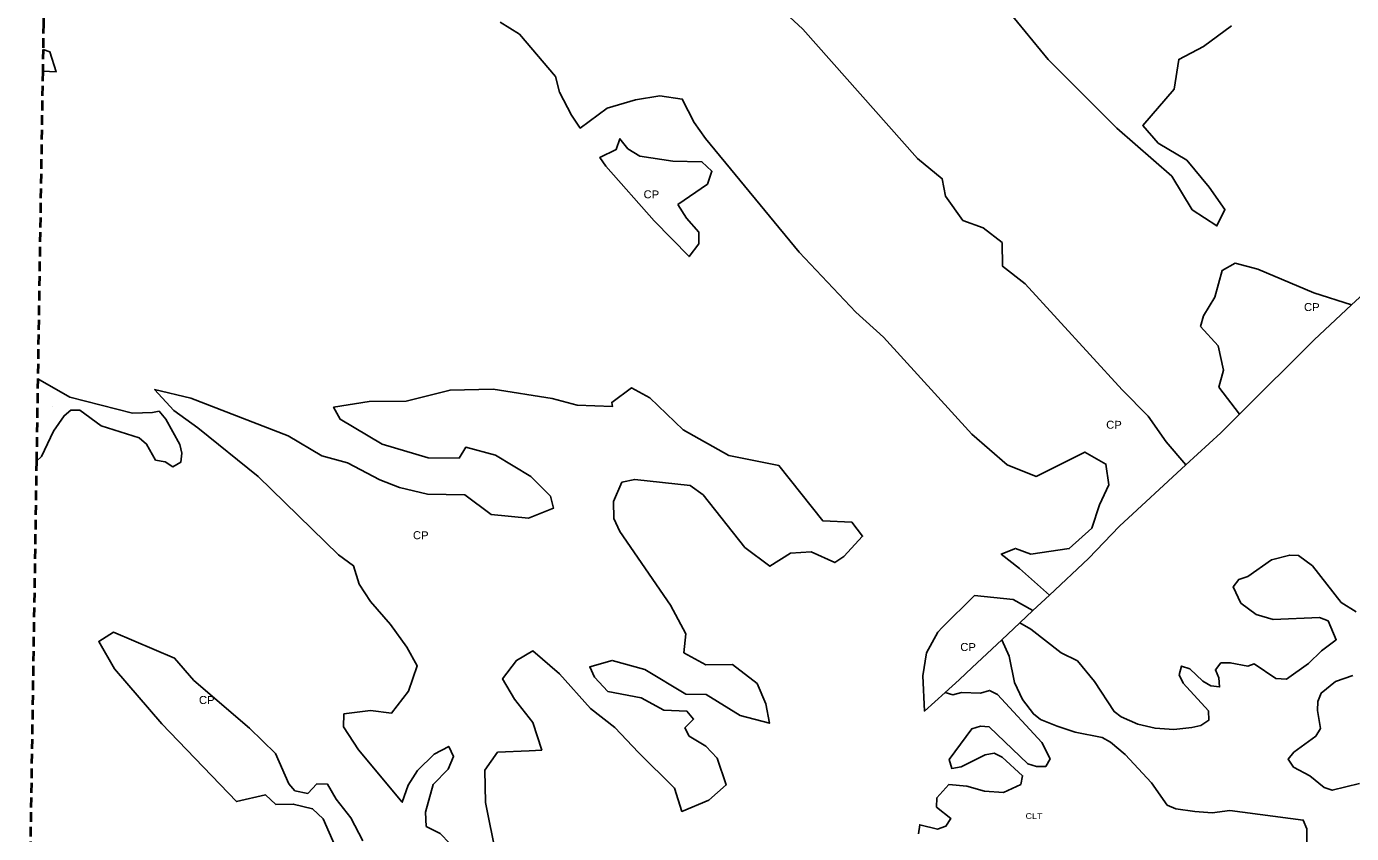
# Model space of a CAD drawing. Extents: x 713589 to 726391, y 7177764 to 7191819.
# Drawn here: x 713612 to 714671, y 7179591 to 7180236 of the extents above; entities that cross this region are included whole.
import ezdxf
from ezdxf.enums import TextEntityAlignment as Align

# ---------------------------------------------------------------- set-up
doc = ezdxf.new("R2010")
doc.units = 0
doc.header["$LTSCALE"] = 2.6
doc.linetypes.add('MEDIUM_DASHED', pattern=[4.5, 3, -1.5])
doc.layers.add('63', color=7, linetype='Continuous', lineweight=25)

msp = doc.modelspace()

# ---------------------------------------------------------------- linework, layer by layer
at = {"layer": '63'}
msp.add_line((714429.85, 7179781.5), (714416.59, 7179769.05), dxfattribs=at)
at = {"layer": '63', "linetype": 'MEDIUM_DASHED', "lineweight": 40}
for points in [[(713626.64, 7180327.97), (713625.21, 7180238.52), (713624.88, 7180217.79), (713624.6, 7180200.34)], [(713624.6, 7180200.34), (713620.67, 7179954.51), (713619.62, 7179888.54)], [(713619.62, 7179888.54), (713613.97, 7179534.19), (713611.65, 7179388.89)]]:
    msp.add_lwpolyline(points, dxfattribs=at)
at = {"layer": '63'}
for points in [[(714176.37, 7180286.4), (714232.62, 7180233.94), (714324.25, 7180130.72), (714344.11, 7180114.45), (714346.74, 7180100.53), (714360.62, 7180080.95), (714376.85, 7180075.29), (714392.08, 7180063.33), (714392.38, 7180044.44), (714410.25, 7180030.49), (714487.99, 7179945.52), (714508.84, 7179924.61), (714523.05, 7179904.04), (714538.93, 7179885.5)], [(714392.06, 7180254.56), (714428.78, 7180209.76), (714483.7, 7180154.98), (714527.71, 7180116.47), (714543.91, 7180089.6), (714563.77, 7180076.64), (714570.09, 7180089.88), (714557.53, 7180107.8), (714539.67, 7180129.37), (714516.82, 7180143), (714504.58, 7180156.94), (714529.49, 7180186.06), (714533.17, 7180209.92), (714553.07, 7180220.16), (714575.3, 7180236.69)], [(714429.85, 7179781.5), (714405.9, 7179802.82), (714391.28, 7179814.19), (714402.61, 7179818.74), (714414.86, 7179814.07), (714445.69, 7179818.66), (714463.62, 7179834.87), (714469.94, 7179853.75), (714477.26, 7179869.65), (714474.97, 7179886.22), (714458.08, 7179895.86), (714419.27, 7179876.37), (714396.09, 7179885.69), (714367.63, 7179910.26), (714297.17, 7179987.6), (714275, 7180007.85), (714229.67, 7180055.65), (714154.59, 7180146.58), (714145.67, 7180159.52), (714136.09, 7180178.1), (714118.19, 7180180.78), (714098.64, 7180177.5), (714076.09, 7180170.9), (714054.56, 7180154.94), (714047.58, 7180165.32), (714038, 7180183.56), (714034.7, 7180196.16), (714005.93, 7180230.01), (713990.37, 7180239.65)], [(713624.88, 7180217.79), (713630.41, 7180216.05), (713635.36, 7180199.81), (713624.6, 7180200.34)], [(714581.76, 7179926.16), (714565.21, 7179947.72), (714568.88, 7179961.3), (714564.61, 7179980.86), (714550.71, 7179996.13), (714553.05, 7180004.74), (714562.02, 7180019.64), (714568.02, 7180041.17), (714578.3, 7180046.79), (714596.52, 7180042.12), (714641.23, 7180023.15), (714671.36, 7180013.46)], [(714671.36, 7180013.46), (714681, 7180022.42)], [(714671.36, 7180013.46), (714641.5, 7179985.7), (714581.76, 7179926.16)], [(713619.62, 7179888.54), (713623.52, 7179892.19), (713633.12, 7179912.62), (713641.71, 7179924.81), (713647, 7179929.42), (713654.26, 7179929.41), (713671.39, 7179916.85), (713701.72, 7179907.23), (713707.65, 7179902.27), (713714.89, 7179889.4), (713722.47, 7179888.06), (713728.73, 7179884.09), (713735.01, 7179887.71), (713736.01, 7179894.97), (713734.37, 7179901.9), (713723.19, 7179922.04), (713717.68, 7179928.47), (713712.46, 7179927.59), (713696.55, 7179926.95), (713646.19, 7179939.63), (713620.67, 7179954.51)], [(714136.97, 7179913.63), (714110.17, 7179939.19), (714095.6, 7179947.17), (714079.68, 7179935.6), (714080.29, 7179932.27), (714052.16, 7179933.32), (714031.96, 7179938.66), (713984.91, 7179946.03), (713950.44, 7179945.42), (713915.3, 7179936.53), (713885.8, 7179936.25), (713857.29, 7179931.66), (713862.58, 7179922.04), (713896.02, 7179902.1), (713932.79, 7179891.1), (713957.64, 7179891.06), (713962.96, 7179899.67), (713986.81, 7179893.33), (714014.95, 7179876.38), (714030.83, 7179860.45), (714033.14, 7179850.83), (714013.24, 7179842.91), (713983.42, 7179845.94), (713962.23, 7179861.55), (713932.41, 7179862.27), (713909.88, 7179867.61), (713894.31, 7179873.6), (713868.49, 7179887.23), (713847.95, 7179892.9), (713820.8, 7179908.85), (713742.97, 7179938.81), (713714.14, 7179945.81), (713729.43, 7179929.2), (713748.56, 7179915.27), (713796.88, 7179876.41), (713861.07, 7179813.67), (713873.17, 7179804.88), (713877.6, 7179790.11), (713886.86, 7179776.18), (713902.74, 7179757.92)], [(714581.76, 7179926.16), (714566.81, 7179911.26), (714538.93, 7179885.5)], [(713987.27, 7179573.18), (713978.73, 7179615.62), (713978.11, 7179641.47), (713988.4, 7179655.7), (714013.73, 7179657), (714023.68, 7179657.51), (714016.61, 7179679.52), (714002.06, 7179698.1), (713992.48, 7179714.36), (714003.44, 7179729.25), (714016.71, 7179736.85), (714037.89, 7179718.59), (714062.7, 7179690.71), (714082.23, 7179675.43), (714101.09, 7179655.56), (714129.87, 7179626.97), (714135.8, 7179608.4), (714157.36, 7179617.31), (714171.3, 7179629.55), (714164.05, 7179651.1), (714155.11, 7179660.73), (714141.54, 7179668.71), (714138.24, 7179675.34), (714145.21, 7179682.29), (714139.91, 7179688.59), (714121.36, 7179689.29), (714103.15, 7179699.26), (714076.64, 7179704.28), (714066.05, 7179715.89), (714062.09, 7179724.18), (714080, 7179729.13), (714106.17, 7179721.79), (714138.95, 7179702.18), (714155.18, 7179701.83), (714182.33, 7179685.21), (714205.84, 7179678.93), (714202.89, 7179694.46), (714195.96, 7179710.71), (714176.43, 7179725.98), (714154.89, 7179725.69), (714137.34, 7179735.33), (714139.02, 7179750.57), (714126.8, 7179773.46), (714086.13, 7179832.18), (714081.51, 7179842.8), (714081.2, 7179856.39), (714087.85, 7179871.62), (714098.13, 7179873.92), (714142.45, 7179869.08), (714152.79, 7179861.57), (714186.2, 7179819.43), (714206.06, 7179804.48), (714222.65, 7179815.06), (714239.22, 7179816.02), (714258.09, 7179807.38), (714265.39, 7179812.33), (714280.33, 7179828.52), (714271.76, 7179839.69), (714248.54, 7179840.86), (714213.48, 7179885), (714173.39, 7179893.02), (714136.97, 7179913.63)], [(714538.93, 7179885.5), (714485.82, 7179836.43), (714460.92, 7179810.68), (714429.85, 7179781.5)], [(714675.17, 7179768.09), (714663.14, 7179775.51), (714640.21, 7179804.82), (714629.06, 7179813.23), (714621.99, 7179813.47), (714607.41, 7179809.62), (714588.49, 7179796.18), (714581.2, 7179793.98), (714576.77, 7179788.13), (714582.82, 7179775.09), (714595.07, 7179766.01), (714608.76, 7179762.01), (714645.77, 7179763.49), (714652.62, 7179760.94), (714659.22, 7179745.69), (714647.39, 7179736.87), (714636.99, 7179726.61), (714619.4, 7179714.16), (714610.89, 7179714.66), (714593.45, 7179726.44), (714588.49, 7179724.7), (714574.35, 7179727.38), (714566.95, 7179727.17), (714562.52, 7179721.76), (714565.16, 7179715.24), (714565.81, 7179707.95), (714558.85, 7179708.73), (714552.45, 7179712.5), (714541.97, 7179722.35), (714535.35, 7179724.68), (714533.68, 7179717.61), (714536.76, 7179710.87), (714556.94, 7179688.74), (714557.26, 7179681.34), (714550.85, 7179677.15), (714543.55, 7179675.51), (714529.41, 7179673.87), (714514.28, 7179675), (714500.47, 7179678.12), (714487.12, 7179684.11), (714481.49, 7179688.32), (714465.95, 7179712.31), (714452.17, 7179728.8), (714439.15, 7179735.34), (714414.98, 7179754.16), (714406.12, 7179759.22)], [(714416.59, 7179769.05), (714400.88, 7179777.97), (714369.74, 7179781.01), (714344.11, 7179755.47), (714340.52, 7179751.89), (714331.55, 7179735.34), (714328.53, 7179716.78), (714329.83, 7179688.68), (714346.29, 7179703.49)], [(714416.59, 7179769.05), (714406.12, 7179759.22), (714391.64, 7179745.63)], [(713902.74, 7179757.92), (713915.96, 7179739.67), (713924.22, 7179724.74), (713917.23, 7179704.54), (713903.61, 7179687), (713886.72, 7179689.01), (713865.5, 7179686.4), (713865.15, 7179676.12), (713877.05, 7179657.55), (713912.11, 7179615.73), (713916.78, 7179629.31), (713924.42, 7179641.23), (713937.7, 7179654.13), (713949.31, 7179660.41), (713953.27, 7179652.45), (713948.94, 7179642.18), (713936.99, 7179629.94), (713930.66, 7179607.75), (713931.3, 7179596.48), (713942.56, 7179590.82), (713988.88, 7179542.69)], [(713880.58, 7179584.96), (713871, 7179603.2), (713859.42, 7179618.14), (713852.48, 7179630.08), (713843.87, 7179630.43), (713836.56, 7179622.81), (713826.29, 7179624.82), (713821.33, 7179630.46), (713810.77, 7179654.67), (713789.92, 7179674.92), (713745.57, 7179713.11), (713730.03, 7179731.03), (713681.34, 7179751.66), (713669.4, 7179744.39), (713681.96, 7179722.49), (713720, 7179678.35), (713779.55, 7179616.28), (713802.76, 7179621.55), (713810.95, 7179613.95), (713824.95, 7179614.22), (713840.52, 7179610.55), (713848.79, 7179602.58), (713863.32, 7179569.74)], [(714391.64, 7179745.63), (714368.04, 7179723.47), (714357.69, 7179713.75), (714346.29, 7179703.49)], [(714391.64, 7179745.63), (714397.49, 7179732.53), (714401.77, 7179711.43), (714408.37, 7179697.94), (714416.97, 7179686.43), (714422.6, 7179681.89), (714435.85, 7179676.68), (714450.42, 7179671.91), (714471.84, 7179667.56), (714478.58, 7179663.68), (714490.49, 7179654.05), (714511.55, 7179631.26), (714524.01, 7179613.46), (714530.85, 7179610.46), (714545.98, 7179608.23), (714560.01, 7179607.32), (714574.15, 7179609.06), (714632.8, 7179601.46), (714635.66, 7179594.6), (714635.64, 7179579.8)], [(714677.7, 7179630.7), (714656.04, 7179625.32), (714649.41, 7179627.65), (714637.94, 7179636.84), (714625.03, 7179643.82), (714620.62, 7179650.13), (714625.16, 7179655.75), (714642.96, 7179668.65), (714646.51, 7179674.72), (714644.21, 7179689.19), (714644.45, 7179696.26), (714647.11, 7179703.11), (714658.61, 7179712.26), (714672.54, 7179717.1)], [(714339.75, 7179619.17), (714349.38, 7179629.87), (714363.74, 7179628.52), (714377.98, 7179624.52), (714393.01, 7179623.62), (714406.82, 7179630), (714408.38, 7179636.96), (714392.06, 7179651.9), (714385.55, 7179655), (714378.47, 7179653.8), (714359.12, 7179644.11), (714351.72, 7179642.8), (714349.63, 7179649.87), (714367.68, 7179674.58), (714374.64, 7179676.67), (714381.71, 7179676), (714412.6, 7179646.56), (714419.55, 7179644.23), (714426.84, 7179644.33), (714430.28, 7179650.51), (714423.67, 7179663.56), (714388.38, 7179701.84), (714381.87, 7179705.16), (714374.69, 7179703.07), (714359.44, 7179703.43), (714352.48, 7179701.79), (714346.29, 7179703.49)], [(714325.12, 7179590.59), (714326.13, 7179597.77), (714340.37, 7179594.21), (714347, 7179596.74), (714350.88, 7179602.81), (714339.41, 7179611.88), (714339.75, 7179619.17)]]:
    msp.add_lwpolyline(points, dxfattribs=at)
msp.add_lwpolyline([(714132.63, 7180093.92), (714139.57, 7180082.98), (714149.5, 7180071.69), (714149.48, 7180062.41), (714141.64, 7180052.22), (714113.72, 7180080.7), (714075.02, 7180124.51), (714070.31, 7180131.51), (714083.32, 7180137.75), (714086.32, 7180146.36), (714092.61, 7180138.4), (714102.21, 7180132.42), (714128.71, 7180128.4), (714151.91, 7180128.03), (714159.85, 7180120.39), (714156.19, 7180110.12)], close=True, dxfattribs=at)

# ---------------------------------------------------------------- texts
for s, height, width, p in [('CP', 0.32, 1.05, (713629.37, 7180207.16)), ('CP', 6.4, 1.05, (714111.37, 7180098.74)), ('CP', 6.4, 1.05, (714639.6, 7180008.58)), ('CP', 0.32, 1.05, (713632.69, 7179931.82)), ('CP', 6.4, 1.05, (714481.36, 7179914.45)), ('CP', 6.4, 1.05, (713926.92, 7179826.08)), ('CP', 6.4, 1.05, (714364.66, 7179736.69)), ('CP', 6.4, 1.05, (713755.76, 7179694.29)), ('CLT', 4.64, 1.15, (714417.4, 7179602.33))]:
    msp.add_text(s, height=height, rotation=359.062, dxfattribs=dict(at, width=width)).set_placement(p, align=Align.CENTER)

doc.saveas('drawing.dxf')
